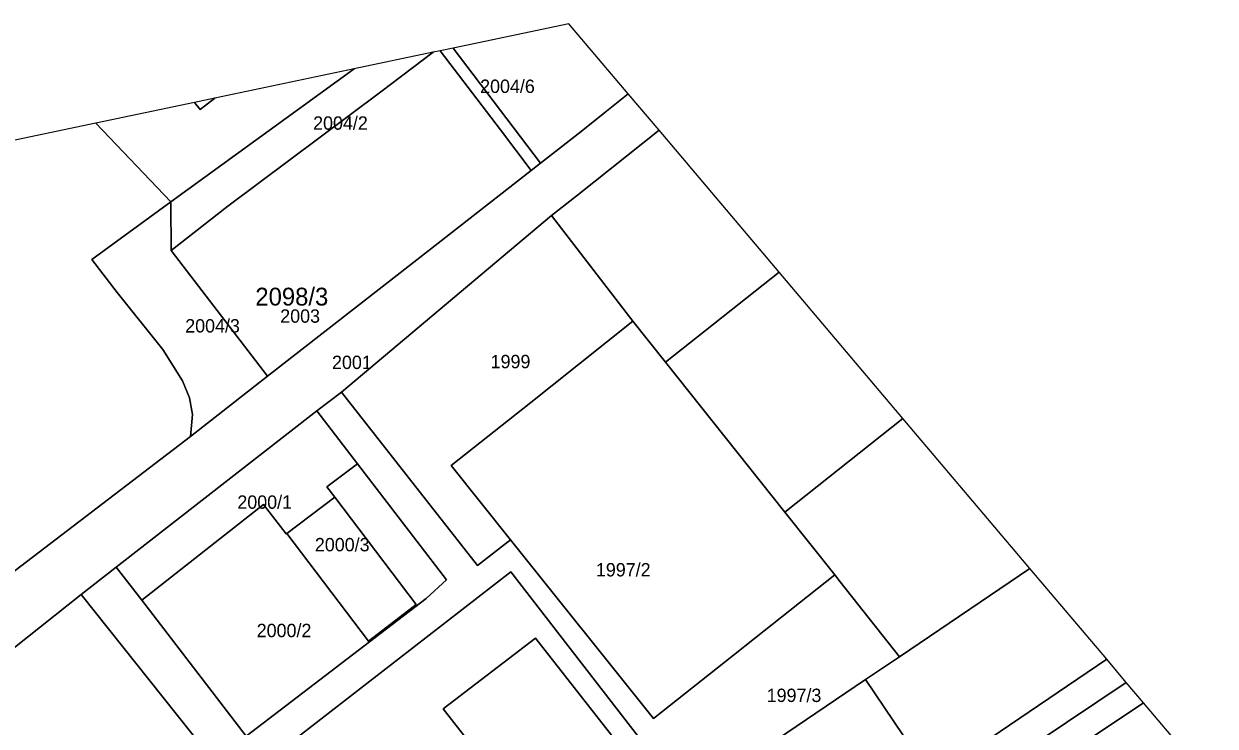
# Model space of a CAD drawing. Extents: x -570698 to -570232, y -1086952 to -1086596.
# Drawn here: x -570431.1 to -570297.5, y -1086675.1 to -1086596.2 of the extents above; entities that cross this region are included whole.
import ezdxf

# ---------------------------------------------------------------- set-up
doc = ezdxf.new("R2010")
doc.units = 0
for name, color, linetype in [('Adresní místo-text', 7, 'Continuous'), ('Parcela-polygon', 7, 'Continuous'), ('Parcela-text', 7, 'Continuous')]:
    doc.layers.add(name, color=color, linetype=linetype)

msp = doc.modelspace()

# ---------------------------------------------------------------- linework, layer by layer
at = {"layer": 'Parcela-polygon'}
for p, q in [((-570385.22, -1086599.43), (-570394.09, -1086601.3)), ((-570384.42, -1086599.27), (-570385.22, -1086599.43)), ((-570382.98, -1086598.96), (-570384.42, -1086599.27)), ((-570394.09, -1086601.3), (-570409.72, -1086604.58)), ((-570412, -1086605.06), (-570423.06, -1086607.38)), ((-570409.72, -1086604.58), (-570412, -1086605.06)), ((-570359.88, -1086608.19), (-570363.33, -1086604.1)), ((-570423.06, -1086607.38), (-570454.26, -1086613.93)), ((-570346.41, -1086624.12), (-570359.88, -1086608.19)), ((-570332.52, -1086640.55), (-570346.41, -1086624.12)), ((-570318.26, -1086657.41), (-570332.52, -1086640.55)), ((-570309.65, -1086667.59), (-570318.26, -1086657.41)), ((-570307.45, -1086670.19), (-570309.65, -1086667.59)), ((-570305.51, -1086672.49), (-570307.45, -1086670.19)), ((-570299.14, -1086680.02), (-570305.51, -1086672.49))]:
    msp.add_line(p, q, dxfattribs=at)
for points in [[(-570363.33, -1086604.1), (-570369.99, -1086596.24), (-570382.98, -1086598.96)], [(-570394.09, -1086601.3), (-570414.64, -1086616.23), (-570414.64, -1086616.46), (-570414.62, -1086621.68), (-570408.26, -1086616.72), (-570391.11, -1086603.86), (-570385.22, -1086599.43)], [(-570385.22, -1086599.43), (-570391.11, -1086603.86), (-570408.26, -1086616.72), (-570414.62, -1086621.68), (-570403.79, -1086635.81), (-570387.07, -1086622.74), (-570374.21, -1086612.69), (-570377.66, -1086608.16), (-570384.42, -1086599.27)], [(-570384.42, -1086599.27), (-570377.66, -1086608.16), (-570374.21, -1086612.69), (-570373.18, -1086611.89), (-570382.98, -1086598.96)], [(-570382.98, -1086598.96), (-570373.18, -1086611.89), (-570368.63, -1086608.33), (-570365.96, -1086606.2), (-570363.33, -1086604.1)], [(-570423.06, -1086607.38), (-570414.64, -1086616.23), (-570394.09, -1086601.3)], [(-570363.33, -1086604.1), (-570365.96, -1086606.2), (-570368.63, -1086608.33), (-570373.18, -1086611.89), (-570374.21, -1086612.69), (-570387.07, -1086622.74), (-570403.79, -1086635.81), (-570412.46, -1086642.58), (-570442.64, -1086665.62), (-570438.26, -1086671.07), (-570424.7, -1086660.31), (-570420.77, -1086657.25), (-570398.26, -1086639.71), (-570395.49, -1086637.59), (-570371.96, -1086617.76), (-570369.01, -1086615.46), (-570359.88, -1086608.19)], [(-570409.72, -1086604.58), (-570411.38, -1086605.86), (-570412, -1086605.06)], [(-570412, -1086605.06), (-570411.38, -1086605.86), (-570409.72, -1086604.58)], [(-570454.26, -1086613.93), (-570488.35, -1086638.54), (-570489.09, -1086646.41), (-570458.09, -1086686.48), (-570443.07, -1086704.77), (-570437.38, -1086700.18), (-570438.47, -1086698.99), (-570433.05, -1086694.85), (-570434.1, -1086693.53), (-570445.98, -1086678.82), (-570451.08, -1086682.93), (-570467.38, -1086662.7), (-570453.79, -1086651.76), (-570442.64, -1086665.62), (-570412.46, -1086642.58), (-570412.23, -1086640.1), (-570412.55, -1086638.24), (-570413.36, -1086636.31), (-570415.56, -1086632.82), (-570420.68, -1086626.4), (-570423.53, -1086622.69), (-570414.64, -1086616.23), (-570423.06, -1086607.38)], [(-570359.88, -1086608.19), (-570369.01, -1086615.46), (-570371.96, -1086617.76), (-570362.81, -1086629.63), (-570359.16, -1086634.22), (-570346.41, -1086624.12)], [(-570346.41, -1086624.12), (-570359.16, -1086634.22), (-570345.77, -1086651.06), (-570332.52, -1086640.55)], [(-570404.01, -1086679.1), (-570376.49, -1086657.78), (-570356.68, -1086683.4), (-570336.7, -1086669.87), (-570332.91, -1086667.31), (-570339.56, -1086658.88), (-570340.17, -1086658.1), (-570349.16, -1086665.26), (-570351.53, -1086667.14), (-570360.49, -1086674.26), (-570376.54, -1086654.18), (-570380.24, -1086657.06), (-570395.49, -1086637.59), (-570398.26, -1086639.71), (-570393.72, -1086645.63), (-570383.74, -1086658.67), (-570386, -1086660.75), (-570406.2, -1086676.21), (-570417.92, -1086660.96), (-570420.77, -1086657.25), (-570424.7, -1086660.31), (-570395.64, -1086696.83)], [(-570332.52, -1086640.55), (-570345.77, -1086651.06), (-570340.17, -1086658.1), (-570339.56, -1086658.88), (-570332.91, -1086667.31), (-570318.26, -1086657.41)], [(-570318.26, -1086657.41), (-570332.91, -1086667.31), (-570336.7, -1086669.87), (-570329.26, -1086680.9), (-570309.65, -1086667.59)], [(-570309.65, -1086667.59), (-570329.26, -1086680.9), (-570327.45, -1086683.58), (-570307.45, -1086670.19)], [(-570307.45, -1086670.19), (-570327.45, -1086683.58), (-570321.07, -1086693.03), (-570318.92, -1086696.23), (-570297.48, -1086681.99)], [(-570305.51, -1086672.49), (-570319.86, -1086682.06), (-570314.36, -1086690.21), (-570299.14, -1086680.02)], [(-570299.14, -1086680.02), (-570314.36, -1086690.21), (-570319.86, -1086682.06), (-570305.51, -1086672.49)]]:
    msp.add_lwpolyline(points, dxfattribs=at)
for points in [[(-570423.53, -1086622.69), (-570420.68, -1086626.4), (-570415.56, -1086632.82), (-570413.36, -1086636.31), (-570412.55, -1086638.24), (-570412.23, -1086640.1), (-570412.46, -1086642.58), (-570403.79, -1086635.81), (-570414.62, -1086621.68), (-570414.64, -1086616.46), (-570414.64, -1086616.23)], [(-570362.81, -1086629.63), (-570371.96, -1086617.76), (-570395.49, -1086637.59), (-570380.24, -1086657.06), (-570376.54, -1086654.18), (-570383.19, -1086645.84), (-570374.26, -1086638.74), (-570371.88, -1086636.84)], [(-570345.77, -1086651.06), (-570359.16, -1086634.22), (-570362.81, -1086629.63), (-570371.88, -1086636.84), (-570374.26, -1086638.74), (-570383.19, -1086645.84), (-570376.54, -1086654.18), (-570360.49, -1086674.26), (-570351.53, -1086667.14), (-570349.16, -1086665.26), (-570340.17, -1086658.1)], [(-570420.77, -1086657.25), (-570417.92, -1086660.96), (-570404.26, -1086650.23), (-570401.73, -1086653.52), (-570401.63, -1086653.46), (-570396.25, -1086649.37), (-570397.14, -1086648.22), (-570393.72, -1086645.63), (-570398.26, -1086639.71)], [(-570417.92, -1086660.96), (-570406.2, -1086676.21), (-570386, -1086660.75), (-570383.74, -1086658.67), (-570393.72, -1086645.63), (-570397.14, -1086648.22), (-570396.25, -1086649.37), (-570387.14, -1086661.45), (-570392.47, -1086665.54), (-570401.63, -1086653.46), (-570401.73, -1086653.52), (-570404.26, -1086650.23)], [(-570401.63, -1086653.46), (-570392.47, -1086665.54), (-570387.14, -1086661.45), (-570396.25, -1086649.37)], [(-570453.79, -1086651.76), (-570467.38, -1086662.7), (-570451.08, -1086682.93), (-570445.98, -1086678.82), (-570434.1, -1086693.53), (-570433.05, -1086694.85), (-570438.47, -1086698.99), (-570437.38, -1086700.18), (-570443.07, -1086704.77), (-570443.22, -1086704.89), (-570435.57, -1086714.25), (-570435.72, -1086714.37), (-570428.66, -1086723.04), (-570408.62, -1086707.18), (-570399.8, -1086700.21), (-570395.64, -1086696.83), (-570424.7, -1086660.31), (-570438.26, -1086671.07), (-570442.64, -1086665.62)], [(-570363.02, -1086706.55), (-570370.68, -1086692.89), (-570356.68, -1086683.4), (-570376.49, -1086657.78), (-570404.01, -1086679.1), (-570376.81, -1086714.9)], [(-570384.09, -1086673.17), (-570373.72, -1086665.22), (-570364.4, -1086677.17), (-570374.63, -1086685.27)], [(-570364.4, -1086677.17), (-570373.72, -1086665.22), (-570384.09, -1086673.17), (-570374.63, -1086685.27)], [(-570355.38, -1086713.04), (-570360.77, -1086704.95), (-570361.85, -1086703.26), (-570363.62, -1086700.62), (-570359.23, -1086697.68), (-570337.92, -1086683.56), (-570337.62, -1086683.47), (-570329.26, -1086680.9), (-570336.7, -1086669.87), (-570356.68, -1086683.4), (-570370.68, -1086692.89), (-570363.02, -1086706.55), (-570360.86, -1086710.41), (-570356.5, -1086716.77), (-570329.42, -1086698.72), (-570330.83, -1086696.57)]]:
    msp.add_lwpolyline(points, close=True, dxfattribs=at)

# ---------------------------------------------------------------- texts
at = {"layer": 'Adresní místo-text'}
msp.add_text('2098/3', height=2, dxfattribs=at).set_placement((-570405.17, -1086627.87))
at = {"layer": 'Parcela-text'}
for s, p in [('2004/6', (-570379.95, -1086604)), ('2004/2', (-570398.69, -1086608.13)), ('2003', (-570402.38, -1086629.8)), ('2004/3', (-570413.04, -1086630.9)), ('2001', (-570396.57, -1086635)), ('1999', (-570378.77, -1086634.91)), ('2000/1', (-570407.19, -1086650.69)), ('2000/3', (-570398.49, -1086655.47)), ('1997/2', (-570366.96, -1086658.29)), ('2000/2', (-570405.02, -1086665.11)), ('1997/3', (-570347.8, -1086672.39))]:
    msp.add_text(s, height=1.5, dxfattribs=at).set_placement(p)

doc.saveas('drawing.dxf')
